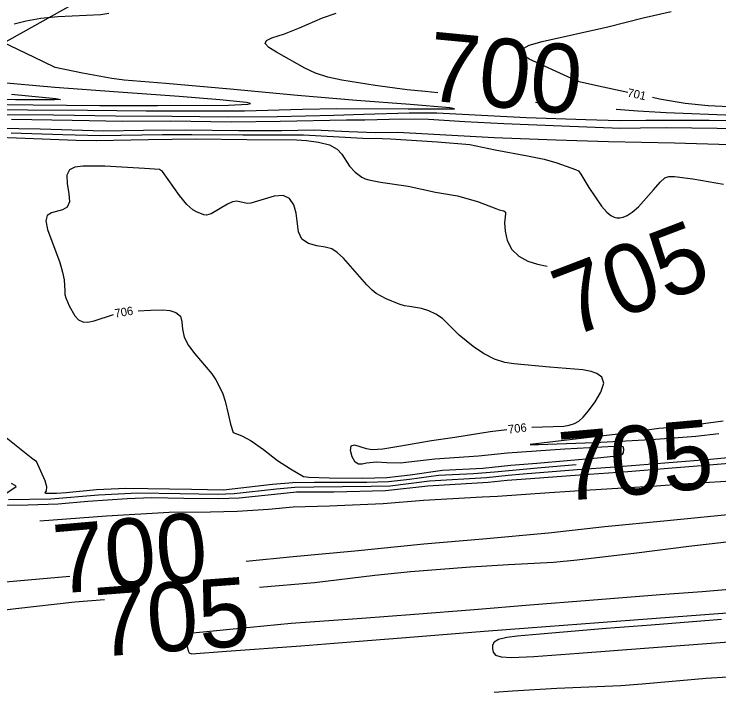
# Model space of a CAD drawing. Extents: x -291892836 to 2945206, y -477993085 to 1832792.
# Drawn here: x 1851909.5 to 1852246.4, y 543592.1 to 543914.3 of the extents above; entities that cross this region are included whole.
import ezdxf

# ---------------------------------------------------------------- set-up
doc = ezdxf.new("R2010")
doc.units = 0
for name, color, linetype in [('DT_X_Contour_Minor', 7, 'Continuous'), ('DT_X_Terrain_Ground_Line', 7, 'Continuous'), ('Level 19', 7, 'Continuous'), ('Level 40', 7, 'Continuous')]:
    doc.layers.add(name, color=color, linetype=linetype)

msp = doc.modelspace()

# ---------------------------------------------------------------- linework, layer by layer
at = {"layer": 'DT_X_Contour_Minor'}
for points in [[(1851909.52, 543909.56), (1851915.34, 543911.11), (1851922.39, 543912.35), (1851930.47, 543913.05), (1851951.03, 543914.14), (1851954.77, 543914.77)], [(1852112.02, 543876.62), (1852106.01, 543877.24), (1852097.49, 543878.09), (1852082.07, 543880.05), (1852066.11, 543882.63), (1852059.45, 543884.17), (1852053.62, 543886.04), (1852048.51, 543888.35), (1852034.91, 543896.1), (1852031.32, 543898.35), (1852029.55, 543900.24), (1852030.24, 543901.7), (1852032.68, 543902.84), (1852038.8, 543904.82), (1852045.89, 543907.71), (1852056.99, 543912.39), (1852063.54, 543914.64)], [(1852202.94, 543876.81), (1852187.39, 543880.07), (1852179.54, 543881.84), (1852175.92, 543883.39), (1852155.68, 543892.78), (1852152.28, 543895.12), (1852152, 543897.3), (1852155.65, 543899.33), (1852161.99, 543901.18), (1852193.29, 543908.1), (1852210.16, 543912.52), (1852223.54, 543915.48)], [(1851890.73, 543868.79), (1851915.96, 543868.54), (1851944.68, 543868.27), (1851972.62, 543868.01), (1852003.01, 543867.99), (1852019.66, 543867.98), (1852047.37, 543868.84), (1852063.83, 543869.12), (1852097.91, 543869.02), (1852120.03, 543869.04), (1852117.85, 543869.38), (1852098.9, 543871.01), (1852073.21, 543873.02), (1852045.02, 543875.33), (1852012.85, 543878.34), (1851982.09, 543881), (1851962.11, 543882.63), (1851956.23, 543883.42), (1851942.26, 543885.95), (1851929.21, 543888.79), (1851923.53, 543891.5), (1851903.38, 543901.08)], [(1851893.84, 543871.18), (1851918.63, 543870.88), (1851950.47, 543870.64), (1851978.11, 543870.58), (1852012, 543870.75), (1852021.22, 543871.17), (1852022.48, 543871.5), (1852020.62, 543871.94), (1852007.88, 543873.28), (1851988.48, 543874.82), (1851959.37, 543876.93), (1851929.06, 543879.24), (1851900.32, 543881.67)], [(1851908.23, 543875.91), (1851929.53, 543873.95), (1851931.72, 543873.49), (1851928.92, 543873.27), (1851910.19, 543873.31), (1851892.72, 543873.7)], [(1852274.35, 543868.82), (1852241.2, 543870.48), (1852230.23, 543871.52), (1852217.99, 543873.65), (1852214.69, 543874.35)], [(1852161.15, 543871.73), (1852161.15, 543871.73), (1852158.67, 543871.97)], [(1851902.42, 543866.3), (1851928.37, 543866.03), (1851957.94, 543865.58), (1851985.03, 543865.4), (1852011.52, 543865.1), (1852035.23, 543865.29), (1852062.34, 543865.97), (1852076.61, 543866.34), (1852098.37, 543867.13), (1852111.64, 543866.98), (1852132.97, 543865.98), (1852154.26, 543864.88), (1852182.77, 543863.94), (1852198.7, 543863.35), (1852211.51, 543863.59), (1852241.8, 543863.49), (1852270.29, 543863.13)], [(1852253.58, 543865.76), (1852221.2, 543867.09), (1852207.69, 543867.79), (1852197.29, 543868.66)], [(1851908.37, 543864.03), (1851937.34, 543863.6), (1851961.5, 543863.14), (1851984.33, 543863.17), (1852013.32, 543862.76), (1852036.76, 543863.01), (1852068.45, 543863.66), (1852077.25, 543863.64), (1852094.78, 543864.2), (1852107.58, 543864.04), (1852124.97, 543862.98), (1852143.57, 543861.93), (1852171.18, 543860.78), (1852199.44, 543859.67), (1852208.95, 543859.89), (1852221.34, 543860.01), (1852245.61, 543859.71), (1852269.25, 543859.24)], [(1851901.41, 543859.77), (1851921.99, 543859.41), (1851952.5, 543858.49), (1851971.43, 543858.74), (1851991.64, 543858.9), (1852017.01, 543858.57), (1852037.34, 543858.63), (1852052.91, 543858.95), (1852069.52, 543858.13), (1852082.2, 543857.72), (1852092.78, 543857.88), (1852107.21, 543857.08), (1852138.93, 543855.27), (1852168.41, 543854.11), (1852193.7, 543853.31), (1852225.18, 543852.77), (1852251.56, 543851.93)], [(1851908.13, 543857.51), (1851932.88, 543856.65), (1851950.66, 543856.14), (1851980.47, 543856.7), (1851994.57, 543856.76), (1852018.86, 543856.48), (1852039.91, 543856.5), (1852047.8, 543856.57), (1852076.22, 543854.97), (1852085.46, 543854.75), (1852089.51, 543854.61), (1852111.95, 543853.25), (1852127.44, 543851.97), (1852139.46, 543849.35), (1852154.98, 543846.5), (1852162.88, 543844.83), (1852168.98, 543843.22), (1852177.88, 543840.03), (1852179.3, 543839.33), (1852180.36, 543837.7), (1852184.28, 543831.31), (1852190.33, 543822.45), (1852192.79, 543819.62), (1852194.73, 543818), (1852196.3, 543817.18), (1852197.67, 543816.8), (1852199.04, 543816.8), (1852200.59, 543817.18), (1852202.52, 543817.99), (1852204.94, 543819.54), (1852207.95, 543822.18), (1852215.17, 543830.28), (1852218.29, 543833.84), (1852220.52, 543835.91), (1852222.52, 543836.69), (1852225.21, 543836.66), (1852233.9, 543835.54), (1852248.54, 543832.94)], [(1851902.03, 543855.42), (1851910.77, 543855.12), (1851939.24, 543854.01), (1851948.81, 543853.78), (1851973.79, 543854.33), (1851996.46, 543854.64), (1852020.71, 543854.38), (1852044.46, 543854.11), (1852049.31, 543853.77), (1852055.1, 543853.06), (1852060.36, 543851.75), (1852063.98, 543849.74), (1852066.2, 543847.36), (1852069.9, 543841.48), (1852072.58, 543838.68), (1852075.76, 543836.37), (1852077.3, 543835.57), (1852079.09, 543834.96), (1852084.74, 543833.95), (1852097.84, 543832.01), (1852110.89, 543829.12), (1852121.5, 543827.45), (1852131.06, 543824.59), (1852139.74, 543821.34), (1852141.42, 543820.71), (1852143.61, 543820.13), (1852144.36, 543819.58), (1852144.47, 543818.7), (1852144, 543814.47), (1852144.23, 543810.54), (1852145.24, 543806), (1852147.36, 543801.74), (1852150.77, 543798.46), (1852155.08, 543796.18), (1852159.77, 543794.72), (1852164.4, 543793.78)], [(1852156.94, 543716.75), (1852172.36, 543717.33), (1852174.89, 543717.76), (1852177.38, 543718.49), (1852179.49, 543719.67), (1852181.56, 543721.6), (1852184.06, 543724.62), (1852187.19, 543728.87), (1852190.04, 543733.58), (1852191.42, 543737.77), (1852190.52, 543740.7), (1852188.1, 543742.47), (1852185.33, 543743.45), (1852181.39, 543744.15), (1852165.41, 543745.52), (1852148.39, 543747.06), (1852144.09, 543747.73), (1852139.22, 543749.29), (1852133.94, 543752.03), (1852128.89, 543755.35), (1852122.22, 543760.73), (1852114.29, 543768.76), (1852111.17, 543770.85), (1852107.7, 543772.42), (1852104.21, 543773.48), (1852098.48, 543774.5), (1852096.15, 543774.86), (1852093.63, 543775.51), (1852087.45, 543778.08), (1852082.55, 543780.68), (1852080.61, 543782.23), (1852078.14, 543784.82), (1852066.98, 543797.59), (1852064.03, 543800.36), (1852061.37, 543801.97), (1852058.27, 543802.86), (1852054.3, 543803.53), (1852050.2, 543804.56), (1852047.01, 543806.63), (1852045.42, 543810.12), (1852044.4, 543819.09), (1852043.3, 543823.09), (1852041.25, 543826.03), (1852038.11, 543827.46), (1852033.88, 543827.14), (1852022.72, 543823.8), (1852020.98, 543823.79), (1852016.07, 543824.8), (1852013.94, 543824.49), (1852011.62, 543823.47), (1852003.75, 543818.71), (1852001.56, 543818.1), (1852000.22, 543818.31), (1851998.35, 543819.14), (1851996.97, 543819.55), (1851994.94, 543820.66), (1851992.17, 543823.18), (1851988.67, 543827.46), (1851980.52, 543838.98), (1851979.01, 543839.92), (1851971.83, 543840.5), (1851952.98, 543841.51), (1851942.48, 543841.58), (1851938.63, 543841.12), (1851936, 543839.86), (1851934.78, 543837.28), (1851934.97, 543833.18), (1851935.73, 543828.49), (1851935.97, 543824.44), (1851934.88, 543821.93), (1851932.74, 543820.65), (1851927.44, 543819.26), (1851925.43, 543817.94), (1851924.65, 543815.41), (1851925.49, 543811.3), (1851931.39, 543795.49), (1851932.68, 543790.94), (1851933.45, 543787.16), (1851933.75, 543782.03), (1851933.84, 543780.22), (1851934.23, 543778.56), (1851935.91, 543774.81), (1851938.63, 543770.02), (1851940.36, 543768.12), (1851942.36, 543767.11), (1851944.76, 543766.98), (1851947.75, 543767.61), (1851957.02, 543770.59)], [(1851968.88, 543772.46), (1851974.76, 543772.78), (1851980.65, 543772.86), (1851983.91, 543772.5), (1851986.92, 543771.57), (1851989, 543769.84), (1851989.75, 543767.14), (1851989.98, 543763.7), (1851990.76, 543759.81), (1851992.89, 543755.78), (1851995.92, 543751.86), (1852004.05, 543742.32), (1852006, 543739.39), (1852007.76, 543736.14), (1852009.28, 543732.7), (1852010.48, 543729.28), (1852011.93, 543723.15), (1852013, 543718.28), (1852014.26, 543714.26), (1852018.44, 543712.64), (1852022.82, 543710.26), (1852028.67, 543706.08), (1852035.38, 543700.93), (1852041.69, 543696.8), (1852047.84, 543693.22), (1852050.4, 543692.92), (1852060.08, 543692.52), (1852076.22, 543692.42), (1852087.7, 543692.77), (1852098.86, 543694.02), (1852114.3, 543696.24), (1852133.61, 543697.13), (1852146.97, 543698.55), (1852159.31, 543699.63), (1852188.44, 543702.15), (1852199.08, 543703.2), (1852200.18, 543703.71), (1852200.76, 543704.49), (1852200.9, 543706.26), (1852200.57, 543707.31), (1852199.95, 543707.54), (1852196.38, 543707.54), (1852172.82, 543706.22), (1852145.34, 543704.36), (1852131.56, 543702.94), (1852110.69, 543701.47), (1852094.01, 543699.61), (1852087.69, 543699.78), (1852082.81, 543700.04), (1852078.04, 543699.54), (1852075.98, 543699.06), (1852074.17, 543699.04), (1852072.55, 543700.13), (1852071.16, 543702.67), (1852070.38, 543705.7), (1852070.65, 543707.88), (1852072.27, 543708.29), (1852077.82, 543706.52), (1852080.71, 543706.06), (1852085.84, 543706.39), (1852093.46, 543707.66), (1852109.01, 543710.37), (1852120.24, 543712.08), (1852137.03, 543714.78), (1852144.99, 543715.67)], [(1852248.38, 543719.72), (1852240.22, 543718.59), (1852228.68, 543716.9), (1852222.23, 543716.43), (1852217.67, 543716.08), (1852202.25, 543713.94), (1852176.48, 543710.87), (1852156.12, 543708.53), (1852160.24, 543708.54), (1852186.96, 543709.43), (1852213.93, 543710.92), (1852224.94, 543711.69), (1852235.41, 543712.5), (1852246.42, 543713.76)], [(1852178.18, 543698.75), (1852161.51, 543697.33), (1852139.16, 543695.28), (1852129.08, 543694.54), (1852112.34, 543693.74), (1852098.48, 543691.82), (1852088.49, 543690.7), (1852078.21, 543690.39), (1852053.18, 543690.32), (1852042.81, 543690.18), (1852033.05, 543689.35), (1852009.68, 543686.7), (1851994.31, 543686.96), (1851963.03, 543687.52), (1851948.91, 543686.86), (1851934.38, 543685.39), (1851929.77, 543685.04), (1851924.48, 543685.1), (1851924.46, 543685.44), (1851925.05, 543686.34), (1851925.26, 543688.2), (1851924.4, 543691.18), (1851920.32, 543700.33), (1851918.54, 543701.5), (1851900.85, 543715.49)], [(1852272.23, 543704.21), (1852242.33, 543701.36), (1852220.58, 543699.64), (1852196.7, 543697.65), (1852178.68, 543696.33), (1852152.86, 543694.3), (1852145.76, 543693.7), (1852135.33, 543692.6), (1852108.07, 543690.98), (1852089.28, 543688.64), (1852080.19, 543688.37), (1852052.85, 543688.04), (1852043.66, 543687.91), (1852035.02, 543687.17), (1852014.74, 543684.85), (1852006.76, 543684.61), (1851988.87, 543684.94), (1851968.7, 543685.23), (1851949.86, 543684.34), (1851927.03, 543682.42), (1851906.84, 543682.01)], [(1852268.1, 543700.89), (1852240.06, 543698.45), (1852222.2, 543697.08), (1852202.82, 543695.49), (1852179.7, 543693.89), (1852156.28, 543692.09), (1852145.15, 543691.28), (1852136.2, 543690.34), (1852107.36, 543688.66), (1852087.11, 543686.42), (1852062.38, 543685.75), (1852044.5, 543685.64), (1852037, 543685), (1852017.08, 543682.87), (1852007.32, 543682.51), (1851990.6, 543682.75), (1851975.16, 543682.98), (1851963.58, 543682.46), (1851944.85, 543681.27), (1851930.61, 543680.05), (1851916.17, 543679.56), (1851889.51, 543679.29)], [(1852259.89, 543691.39), (1852229.13, 543689.58), (1852216.63, 543688.63), (1852184.88, 543686.75), (1852165.38, 543685.38), (1852140.58, 543683.7), (1852133.25, 543683.25), (1852105.25, 543681.68), (1852085.89, 543680.19), (1852060.26, 543679.07), (1852042.92, 543678.49), (1852031.18, 543677.36), (1852016.22, 543676.49), (1852003.42, 543676.08), (1851983.65, 543676.07), (1851953.65, 543674.27), (1851921.83, 543671.82)], [(1851906.09, 543685.4), (1851910.46, 543688.44), (1851910.13, 543688.9), (1851908.24, 543689.88)], [(1852020.48, 543652.7), (1852042.96, 543654.91), (1852072.33, 543657.67), (1852105.4, 543661.03), (1852133.64, 543663.45), (1852164.95, 543666.34), (1852191.96, 543669.37), (1852221.66, 543672.23), (1852250.7, 543674.99)], [(1852026.8, 543640.23), (1852053.07, 543642.6), (1852081.91, 543646.06), (1852098.98, 543647.8), (1852127.62, 543650.01), (1852145.9, 543651.1), (1852167.39, 543652.28), (1852178.67, 543653.38), (1852207.07, 543656.79), (1852232.1, 543659.87), (1852250.09, 543661.92), (1852262.78, 543662.79), (1852288.97, 543664.27)], [(1851660.16, 543619.64), (1851681.71, 543621.29), (1851713.24, 543624.28), (1851742.4, 543626.87), (1851769.69, 543629.31), (1851801.72, 543632.12), (1851828.15, 543634.38), (1851845.91, 543636.02), (1851868.28, 543638.96), (1851887.33, 543641.24), (1851916.29, 543643.84), (1851936.17, 543645.52)], [(1852273.93, 543641.07), (1852238.34, 543638.15), (1852218.37, 543636.57), (1852184.59, 543633.92), (1852156, 543631.63), (1852129.43, 543629.49), (1852100.96, 543627.17), (1852075.74, 543625.33), (1852041.93, 543622.88), (1852022.31, 543621.07), (1851991.77, 543618.06), (1851991.8, 543616.3), (1851992.26, 543611.9), (1851992.67, 543609.93), (1851993.23, 543608.85), (1851994.31, 543608.46), (1852011, 543609.67), (1852046.56, 543612.26), (1852074.44, 543614.48), (1852100.83, 543616.55), (1852134.16, 543619.21), (1852155.25, 543620.85), (1852189.09, 543623.37), (1852216.43, 543625.46), (1852246.01, 543627.69), (1852274.15, 543629.75)], [(1851656.18, 543605.84), (1851686.02, 543608.16), (1851702.84, 543609.25), (1851729.01, 543610.92), (1851753.79, 543613.15), (1851786.51, 543616.17), (1851820.34, 543619.47), (1851850.78, 543622.98), (1851878.44, 543626.29), (1851910.31, 543630.03), (1851938.51, 543633.32), (1851952.77, 543634.44)], [(1852247.64, 543624.91), (1852213.99, 543622.21), (1852192.46, 543620.56), (1852160.99, 543617.86), (1852149.93, 543616.85), (1852145.07, 543616.21), (1852141.09, 543615.28), (1852138.94, 543614.03), (1852138.23, 543612.53), (1852138.24, 543610.9), (1852138.51, 543609.27), (1852139.61, 543607.87), (1852142.37, 543606.97), (1852147.22, 543606.71), (1852157.93, 543607.23), (1852179.42, 543608.81), (1852210.86, 543611.09), (1852236.36, 543613.04), (1852261.85, 543614.97)], [(1852138.98, 543590.09), (1852147.74, 543590.72), (1852168.9, 543592.05), (1852199.53, 543593.32), (1852209.65, 543594.06), (1852240.25, 543596.78), (1852250.61, 543597.42), (1852282.39, 543598.97), (1852302.5, 543600.68), (1852327.16, 543602.75), (1852346.89, 543604.1), (1852376.6, 543606.61), (1852391.5, 543607.51), (1852420.69, 543609.17), (1852444.43, 543610.84), (1852470.62, 543612.79), (1852501.13, 543615.73), (1852524.64, 543618.3), (1852538.83, 543620.21), (1852539.36, 543620.28)]]:
    msp.add_lwpolyline(points, dxfattribs=at)
at = {"layer": 'Level 40'}
msp.add_line((1851996.6, 543951.97), (1851683.81, 543776.99), dxfattribs=at)

# ---------------------------------------------------------------- texts
at = {"layer": 'DT_X_Terrain_Ground_Line'}
for s, rotation, p in [('700', 354.489, (1852106.02, 543873.12)), ('705', 20.9072, (1852175.55, 543759.51)), ('705', 5.1165, (1852171.47, 543681.34)), ('700', 4.9446, (1851929.73, 543637.07)), ('705', 4.3258, (1851949.69, 543606.97))]:
    msp.add_text(s, height=33, rotation=rotation, dxfattribs=at).set_placement(p)
at = {"layer": 'Level 19'}
for s, rotation, p in [('701', 348.1521, (1852202.39, 543874.88)), ('706', 9.2762, (1851957.91, 543769.16)), ('706', 6.3942, (1852145.85, 543713.76))]:
    msp.add_text(s, height=4, rotation=rotation, dxfattribs=at).set_placement(p)

doc.saveas('drawing.dxf')
